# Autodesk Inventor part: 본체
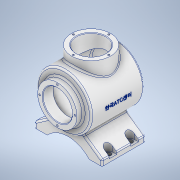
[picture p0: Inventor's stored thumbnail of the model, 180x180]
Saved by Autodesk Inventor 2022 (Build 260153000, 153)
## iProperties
Created: 2023-04
Part Number: 본체
Material: 알루미늄 6061
Document SubType Name: Modeling
Designer: ADMIN_PC
Density: 2.7 g/cm^3
Appearance: 알루미늄 - 평지
Mass: 1296.71 g
Surface Area: 1060.45 cm^2
Volume: 480.263 cm^3
Author: ADMIN_PC
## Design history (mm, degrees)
sketch "스케치1"
  geometry: L1 (-10.134, 0)-(60.805, 0) reference; L2 (0, -87.453)-(0, 84.575) reference; L3 (27, 60)-(36, 60); L4 (36, 60)-(36, 48); L5 (36, 48)-(50, 48); L6 (50, 48)-(50, -48.336); L7 (27, 60)-(27, 41); L8 (27, 41)-(43, 41); L9 (43, 41)-(43, -43.887); L10 (0, -53)-(0, -60); A1 r 113 centre (0, 53) between (0, -60) and (50, -48.336); A2 r 106 centre (0, 53) between (0, -53) and (43, -43.887); 1 further point
  constraints: 16 end point, 4 perpendicular, 4 point on circle, 2 centre point, 2 horizontal, 2 point on line, 1 collinear, 1 vertical
  dimensions: "d0" = 113 radius of A1; "d1" = 120 distance from line of L10.end L3; "d2" = 7 radial gap between concentric circles of A1 A2; "d4" = 86 diameter of L9 L2; "d5" = 100 diameter of L6 L2; "d6" = 108 distance from line of L10.end L5; "d7" = 19 distance between parallel lines of L8 L3; "d8" = 60 distance between parallel lines of L3 L1; "d9" = 72 diameter of L4 L2; "d10" = 54 diameter of L7 L2
revolve "회전1" sketch "스케치1" stored, may be unused: angle "d11" = 90 deg
sketch "스케치3"
  geometry: L1 (-70, 0)-(70, 0) reference; L2 (0, -70)-(0, 70) reference; L3 (23.303, -39.904)-(62, -67); L4 (62, -67)-(62, -77); L5 (62, -77)-(38.5, -77); L6 (-23.088, -60)-(19.564, -60); L7 (-62, -77)-(-38.5, -77); L8 (-62, -67)-(-62, -77); L9 (-23.303, -39.904)-(-62, -67); L10 (-23.303, -39.904)-(-10.457, -46.161); L11 (-10.457, -46.161)-(0, -46.161); L12 (10.206, -46.161)-(23.303, -39.904); L13 (0, -46.161)-(10.206, -46.161); A1 r 52.096 centre (0, -112.096) between (38.5, -77) and (-38.5, -77); 1 further point
  constraints: 22 end point, 3 point on line, 3 symmetric about line, 2 horizontal, 2 perpendicular, 2 point on circle, 1 centre point, 1 collinear, 1 tangent, 1 vertical
  dimensions: "d12" = 55 deg angle of L4 L3; "d13" = 10 distance of L3.end L4.end; "d14" = 17 distance between parallel lines of L5 L6; "d15" = 77 distance of L7.end L5.end; "d16" = 77 distance between parallel lines of L5 L1; "d17" = 124 distance between parallel lines of L4 L8; "d18" = 46.16052 distance between parallel lines of L1 L13; "d20" = 10.20589 distance of L11.end L12.start; "d21" = 154.033 deg angle of L11 L10; "d22" = 12.84638 horizontal distance of L9.start L10.end
extrude "돌출1" join sketch "스케치3" stored distance "d23" = 80; taper "d24" = 0 deg
sketch "스케치5"
  geometry: L1 (-125.3, -40)-(48.3, -40) reference; L2 (-38.5, -124)-(-38.5, 44) reference; L3 (0, 0)-(23.5, 0) reference; L4 (23.5, -80)-(23.5, 0) reference; 5 further points
  constraints: 2 symmetric about line
  dimensions: "d25" = 20 distance from line of L3 point (15.5, -20); "d26" = 40 distance of point (15.5, -60) point (15.5, -20); "d27" = 8 distance from line of L4 point (15.5, -20); "d28" = 8 distance from line of L4 point (15.5, -60)
hole "구멍1" sketch "스케치5" at (15.5, -20), (15.5, -60), (-92.5, -20), (-92.5, -60) diameter "d29" = 9; stored, may be unused: countersink angle "d33" = 90 deg, drill point angle "d35" = 0 deg; dims "d30" = 8, "d31" = 4, "d32" = 2, "d34" = 6
sketch "스케치6"
  geometry: L1 (-32.8, 20)-(140.8, 20) reference; L2 (54, -64)-(54, 104) reference; L3 (0, -7)-(-8, -7); L4 (-8, 60)-(-8, -20) reference; L5 (0, 7)-(-8, 7); L6 (-8, -7)-(-8, 7); L7 (-8, 47)-(-8, 33); L8 (0, 47)-(-8, 47); L9 (0, 33)-(-8, 33); L10 (116, -7)-(116, 7); L11 (108, -7)-(116, -7); L12 (108, 7)-(116, 7); L13 (116, 47)-(116, 33); L14 (108, 33)-(116, 33); L15 (108, 47)-(116, 47); C1 r 4.5 at (0, 0) reference; A1 r 7 centre (0, 0) between (0, -7) and (0, 7); A2 r 7 centre (0, 40) between (0, 33) and (0, 47); A3 r 7 centre (108, 0) between (108, 7) and (108, -7); A4 r 7 centre (108, 40) between (108, 47) and (108, 33); 1 further point
  constraints: 24 end point, 15 symmetric about line, 8 point on circle, 4 centre point, 2 point on line, 1 coincident, 1 collinear, 1 horizontal, 1 parallel, 1 tangent, 3 other
  dimensions: "d36" = 14 distance between parallel lines of L5 L3; "d37" = 7 distance from line of C1.centre L5
extrude "돌출2" cut sketch "스케치6" distance "d38" = 30; taper "d39" = 0 deg
node "작업 평면1"
sketch "스케치7"
  geometry: L1 (-36, 60)-(36, 60) reference; L2 (0, -84)-(0, 84) reference; C1 r 36 at (0, -2); 1 further point
  constraints: 1 centre point, 1 coincident, 1 point on line
  dimensions: "d41" = 72 diameter of C1; "d74" = 62 distance from line of L1 point (0, -2)
extrude "돌출3" join sketch "스케치7" stored distance "d42" = 30; taper "d43" = 0 deg
sketch "스케치8"
  geometry: C1 r 27 at (0, 0); C2 r 36 at (0, 0) reference; 1 further point
  constraints: 2 coincident, 1 centre point
  dimensions: "d44" = 54 diameter of C1
extrude "돌출4" cut sketch "스케치8" stored distance "d45" = 10; taper "d46" = 0 deg
fillet "모깎기1" dims "d47" = 3
chamfer "모따기1" distance "d48" = 1; stored, may be unused: second distance "d49" = 2, angle "d50" = 45 deg
fillet "모깎기2" dims "d51" = 3
fillet "모깎기3" dims "d52" = 3
sketch "스케치10"
  geometry: L1 (0, -105.4)-(0, 93.4) reference; L2 (-86.8, 0)-(86.8, 0) reference; A1 r 32.5 centre (0, 0) between (0, 32.5) and (32.5, 0); 3 further points
  constraints: 4 point on circle, 4 point on line, 1 centre point, 1 coincident
  dimensions: "d53" = 65 diameter of A1
hole "구멍2" sketch "스케치10" at (0, 32.5), (32.5, 0), (0, -32.5), (-32.5, 0) diameter "d54" = 3.242; stored, may be unused: countersink angle "d58" = 90 deg, drill point angle "d60" = 118 deg; dims "d55" = 8, "d56" = 4, "d57" = 2, "d59" = 10
node "작업 평면2"
sketch "스케치12"
  geometry: L1 (-36, 60)-(36, 60) reference; 2 further points
  constraints: 1 other
  dimensions: "d70" = 0 horizontal distance of point (0, 0) point (0, -2); "d71" = 62 distance from line of L1 point (0, -2)
feature "엠보싱1" sketch "스케치12" dims "d0" = 113, "d1" = 120, "d2" = 7, "d4" = 86, "d5" = 100, "d6" = 108, "d7" = 19, "d8" = 60, "d9" = 72, "d10" = 54, "d72" = 0.5, "d73" = 0
sketch "스케치13" dims "d75" = 65
  geometry: L1 (0, 82)-(0, -86) reference; C1 r 36 at (0, 0) reference; 3 further points
  constraints: 1 coincident, 1 point on line, 1 vertical alignment, 2 other
hole "구멍4" sketch "스케치13" at (0, 32.5) diameter "d76" = 3.242; stored, may be unused: countersink angle "d80" = 90 deg, drill point angle "d82" = 118 deg; dims "d77" = 8, "d78" = 4, "d79" = 2, "d81" = 10
node "솔리드1"
pattern_circular "원형 패턴1" dims angle "d84" = 360 deg
feature "A9D066F2-1C7D-4E18-AEED-F7BC21143FA4" dims "d29" = 9, "d30" = 8, "d31" = 4, "d32" = 2, "d33" = 90 deg, "d34" = 6, "d35" = 0
other parameters: "d40" = 65
